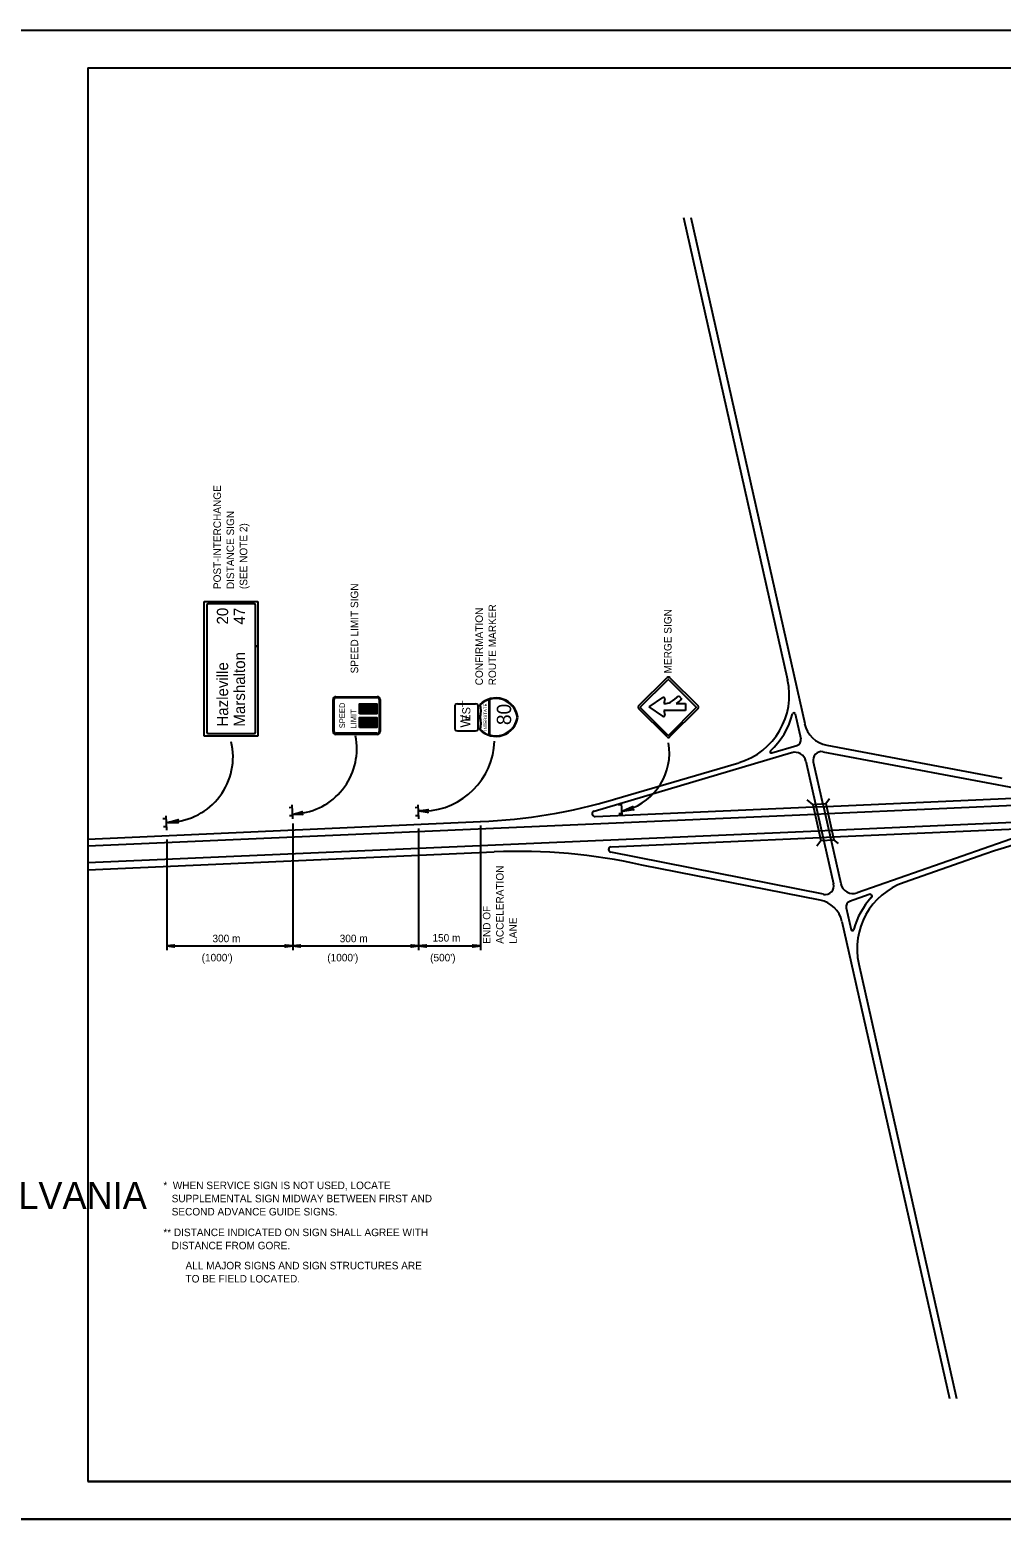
# Model space of a CAD drawing. Extents: x 640994 to 644422, y 298458 to 299646.
# Drawn here: x 641852 to 642240, y 299044 to 299646 of the extents above; entities that cross this region are included whole.
import ezdxf

# ---------------------------------------------------------------- set-up
doc = ezdxf.new("R2010")
doc.units = 0
for name, color, linetype in [('1', 7, 'Continuous'), ('2', 7, 'Continuous'), ('3', 7, 'Continuous'), ('XCS-GRID-MIN', 7, 'Continuous')]:
    doc.layers.add(name, color=color, linetype=linetype)

# ---------------------------------------------------------------- blocks, each defined once
blk = doc.blocks.new('RARROW')
at = {"layer": '3'}
blk.add_lwpolyline([(-2.2695, 0.285), (-2.184875, 0.12075), (0, 0), (-2.2695, 0.285), (-2.38575, 0.384625), (0, 0), (-2.183125, -0.108), (-2.262875, -0.2705), (0, 0), (-2.38575, -0.379125), (-2.262875, -0.2705)], dxfattribs=at)

msp = doc.modelspace()

# ---------------------------------------------------------------- linework, layer by layer
at = {"layer": '1'}
for p, q in [((641875.31, 299630.63), (642661.31, 299630.63)), ((641875.31, 299630.63), (641875.31, 299066.63)), ((642661.31, 299066.63), (641875.31, 299066.63)), ((641875.31, 299066.63), (642461.31, 299066.63))]:
    msp.add_line(p, q, dxfattribs=at)
at = {"layer": '2'}
for p, q in [((642112.94, 299570.88), (642154.44, 299386.5)), ((642115.94, 299570.88), (642161.31, 299369)), ((641921.81, 299364), (641921.81, 299417.75)), ((641921.81, 299417.75), (641943.19, 299417.75)), ((641922.81, 299416.25), (641922.81, 299365.5)), ((641941.69, 299416.75), (641923.31, 299416.75)), ((641942.19, 299399.88), (641942.19, 299416.25)), ((641943.19, 299417.75), (641943.19, 299399.88)), ((641942.19, 299399.88), (641943.19, 299399.88)), ((641943.19, 299399.88), (641942.19, 299399.88)), ((641942.19, 299365.5), (641942.19, 299399.88)), ((641943.19, 299399.88), (641943.19, 299364)), ((641932.44, 299390.88), (641932.44, 299390.88)), ((642095.06, 299376), (642106.44, 299387.38)), ((642095.81, 299375.63), (642106.69, 299386.5)), ((642107.06, 299386.5), (642117.94, 299375.63)), ((642107.44, 299387.38), (642118.81, 299376)), ((641973.19, 299365.88), (641973.19, 299378.63)), ((641973.56, 299365.88), (641973.56, 299378.63)), ((641974.31, 299379.63), (641990.81, 299379.63)), ((641974.31, 299379.38), (641990.81, 299379.38)), ((641991.56, 299378.63), (641991.56, 299365.88)), ((641991.94, 299378.63), (641991.94, 299365.88)), ((642035.44, 299364.5), (642035.44, 299378.63)), ((642035.69, 299364.5), (642035.69, 299378.63)), ((642099.31, 299375.63), (642104.69, 299379.38)), ((642105.56, 299378.63), (642105.06, 299377)), ((642111.06, 299380), (642112.31, 299378.75)), ((641987.69, 299372.88), (641983.69, 299376.88)), ((641986.94, 299372.88), (641983.69, 299376.25)), ((641986.19, 299372.88), (641983.69, 299375.5)), ((641985.56, 299372.88), (641983.69, 299374.88)), ((641984.94, 299372.88), (641983.69, 299374.13)), ((641984.19, 299372.88), (641983.69, 299373.38)), ((641988.44, 299372.88), (641984.44, 299376.88)), ((641989.06, 299372.88), (641985.06, 299376.88)), ((641989.81, 299372.88), (641985.81, 299376.88)), ((641990.44, 299372.88), (641986.44, 299376.88)), ((641990.69, 299373.38), (641987.19, 299376.88)), ((641990.69, 299374.13), (641987.94, 299376.88)), ((641990.69, 299374.75), (641988.69, 299376.88)), ((641990.69, 299375.38), (641989.31, 299376.88)), ((641990.69, 299376.13), (641990.06, 299376.88)), ((642021.94, 299366.63), (642021.94, 299376.38)), ((642022.81, 299376.88), (642029.94, 299376.88)), ((642030.94, 299376.38), (642030.94, 299366.63)), ((642031.94, 299376.5), (642031.94, 299376.5)), ((642106.44, 299363.63), (642095.06, 299375)), ((642106.69, 299364.38), (642095.81, 299375.25)), ((642104.69, 299371.88), (642099.31, 299375.63)), ((642105.06, 299377), (642105.44, 299377)), ((642113.81, 299374.25), (642105.06, 299374.25)), ((642105.06, 299374.25), (642105.56, 299372.63)), ((642117.94, 299375.25), (642107.06, 299364.38)), ((642117.94, 299375.25), (642107.06, 299364.38)), ((642118.81, 299375), (642107.44, 299363.63)), ((642110.06, 299377), (642113.81, 299377)), ((642113.81, 299377), (642113.81, 299374.25)), ((642157.56, 299372.88), (642159.81, 299362.88)), ((641982.56, 299372.13), (641982.56, 299372.13)), ((641987.69, 299367.38), (641983.69, 299371.38)), ((641986.94, 299367.38), (641983.69, 299370.75)), ((641986.19, 299367.38), (641983.69, 299370)), ((641985.56, 299367.38), (641983.69, 299369.38)), ((641984.94, 299367.38), (641983.69, 299368.63)), ((641984.19, 299367.38), (641983.69, 299367.88)), ((641988.44, 299367.38), (641984.44, 299371.38)), ((641989.06, 299367.38), (641985.06, 299371.38)), ((641989.81, 299367.38), (641985.81, 299371.38)), ((641990.44, 299367.38), (641986.44, 299371.38)), ((641990.69, 299367.88), (641987.19, 299371.38)), ((641990.69, 299368.63), (641987.94, 299371.38)), ((641990.69, 299369.25), (641988.69, 299371.38)), ((641990.69, 299369.88), (641989.31, 299371.38)), ((641990.69, 299370.63), (641990.06, 299371.38)), ((642026.44, 299371.5), (642026.44, 299371.5)), ((642031.94, 299371.5), (642031.94, 299371.5)), ((642039.31, 299371.5), (642039.31, 299371.5)), ((641943.19, 299364), (641921.81, 299364)), ((641923.31, 299365), (641941.69, 299365)), ((641990.81, 299365.13), (641974.31, 299365.13)), ((641990.81, 299364.63), (641974.31, 299364.63)), ((642029.94, 299366), (642022.81, 299366)), ((642031.94, 299366.5), (642031.94, 299366.5)), ((642077.31, 299334), (642156.06, 299357.38)), ((642148.19, 299357.25), (642158.19, 299360.25)), ((642168.56, 299357.75), (642253.56, 299341.75)), ((642170.19, 299360.38), (642239.94, 299347.25)), ((642170.44, 299333.13), (642661.31, 299354.84)), ((642085.44, 299338.88), (642135.06, 299353.38)), ((642161.78, 299354.04), (642165.56, 299336.88)), ((642164.72, 299353.7), (642168.56, 299336.75)), ((642171.94, 299326.5), (642661.31, 299347.96)), ((641956.69, 299336.5), (641956.94, 299331)), ((642006.94, 299336.5), (642007.19, 299331)), ((642088.06, 299336.5), (642087.06, 299336.38)), ((642088.06, 299337.5), (642088.31, 299332)), ((642164.56, 299336.75), (642162.31, 299338.5)), ((642164.56, 299336.75), (642169.69, 299337.13)), ((642164.56, 299336.75), (642167.81, 299322.38)), ((642165.56, 299336.88), (642172.81, 299305)), ((642168.56, 299337), (642175.69, 299305.13)), ((642169.69, 299337.13), (642171.19, 299339.13)), ((642169.69, 299337.13), (642172.94, 299322.63)), ((642169.81, 299335.88), (642253.44, 299339.63)), ((641875.31, 299320.21), (642165.44, 299332.88)), ((641906.44, 299331), (641905.31, 299331)), ((641906.44, 299332.13), (641906.69, 299326.5)), ((641956.69, 299335.5), (641955.69, 299335.38)), ((641956.94, 299332.13), (641955.81, 299332.13)), ((642006.94, 299335.5), (642005.94, 299335.38)), ((642007.19, 299332.13), (642006.06, 299332.13)), ((642077.69, 299331.88), (642164.81, 299335.75)), ((642088.31, 299333), (642087.19, 299333)), ((642164.81, 299335.75), (642169.81, 299335.88)), ((642165.44, 299332.88), (642170.44, 299333.13)), ((641875.31, 299322.84), (642031.94, 299329.88)), ((641875.31, 299313.59), (642166.81, 299326.25)), ((641906.56, 299327.75), (641905.56, 299327.75)), ((641957.06, 299329.13), (641957.06, 299278.63)), ((642007.31, 299328.75), (642007.31, 299328.75)), ((642007.31, 299327.13), (642007.31, 299278.63)), ((642031.94, 299328.38), (642031.94, 299278.63)), ((642166.81, 299326.25), (642171.94, 299326.5)), ((642172.56, 299323.75), (642248.94, 299327.13)), ((642249.31, 299324.88), (642182.23, 299301.42)), ((641906.81, 299324.38), (641906.81, 299324.38)), ((641906.81, 299322.75), (641906.81, 299278.63)), ((642084.19, 299319.75), (642167.44, 299323.5)), ((642166.19, 299320.25), (642167.81, 299322.38)), ((642167.44, 299323.5), (642172.56, 299323.75)), ((642167.81, 299322.38), (642172.94, 299322.63)), ((642174.81, 299321.13), (642172.94, 299322.63)), ((641875.31, 299310.59), (642037.44, 299317.75)), ((642168.81, 299300.88), (642083.94, 299317.63)), ((642167.44, 299298.5), (642096.31, 299312.5)), ((642233.19, 299316.88), (642200.94, 299305.63)), ((642186.98, 299300.74), (642179.19, 299298)), ((642177.83, 299295.44), (642179.81, 299286.75)), ((642176.19, 299290), (642219.06, 299099.75)), ((641906.81, 299280.25), (641957.06, 299280.25)), ((641957.06, 299280.25), (642007.31, 299280.25)), ((642007.31, 299280.25), (642031.94, 299280.25)), ((642182.94, 299273), (642221.81, 299099.75))]:
    msp.add_line(p, q, dxfattribs=at)
for points in [[(641983.69, 299372.88), (641983.69, 299376.88), (641990.69, 299376.88), (641990.69, 299372.88)], [(641983.69, 299367.38), (641983.69, 299371.38), (641990.69, 299371.38), (641990.69, 299367.38)]]:
    msp.add_lwpolyline(points, close=True, dxfattribs=at)
for points in [[(641911.32, 299329.58), (641911.07, 299329.71), (641907.19, 299329.58), (641911.32, 299329.58), (641911.44, 299329.33), (641907.19, 299329.58), (641911.07, 299330.21), (641911.19, 299330.46), (641907.19, 299329.58), (641911.32, 299330.71), (641911.19, 299330.46)], [(641960.83, 299332.82), (641960.66, 299333.04), (641957.29, 299332.7), (641960.83, 299332.82), (641961.1, 299332.74), (641957.29, 299332.7), (641960.6, 299333.41), (641960.68, 299333.68), (641957.29, 299332.7), (641960.88, 299333.97), (641960.68, 299333.68)], [(642010.81, 299333.63), (642010.69, 299333.88), (642007.31, 299334.13), (642010.81, 299333.63), (642011.06, 299333.5), (642007.31, 299334.13), (642010.69, 299334.25), (642010.81, 299334.5), (642007.31, 299334.13), (642011.06, 299334.75), (642010.81, 299334.5)], [(642092.94, 299334.75), (642092.56, 299335), (642088.81, 299334), (642092.94, 299334.75), (642093.19, 299334.63), (642088.81, 299334), (642092.56, 299335.38), (642092.56, 299335.75), (642088.81, 299334), (642092.69, 299335.88), (642092.56, 299335.75)], [(641909.67, 299279.89), (641909.56, 299280.1), (641906.81, 299280.25), (641909.67, 299279.89), (641909.81, 299279.77), (641906.81, 299280.25), (641909.56, 299280.39), (641909.66, 299280.59), (641906.81, 299280.25), (641909.81, 299280.73), (641909.66, 299280.59)], [(641954.21, 299280.61), (641954.31, 299280.4), (641957.06, 299280.25), (641954.21, 299280.61), (641954.06, 299280.74), (641957.06, 299280.25), (641954.32, 299280.12), (641954.22, 299279.91), (641957.06, 299280.25), (641954.06, 299279.77), (641954.22, 299279.91)], [(641959.92, 299279.89), (641959.81, 299280.1), (641957.06, 299280.25), (641959.92, 299279.89), (641960.06, 299279.77), (641957.06, 299280.25), (641959.81, 299280.39), (641959.91, 299280.59), (641957.06, 299280.25), (641960.06, 299280.73), (641959.91, 299280.59)], [(642004.46, 299280.61), (642004.56, 299280.4), (642007.31, 299280.25), (642004.46, 299280.61), (642004.31, 299280.74), (642007.31, 299280.25), (642004.57, 299280.12), (642004.47, 299279.91), (642007.31, 299280.25), (642004.31, 299279.77), (642004.47, 299279.91)], [(642010.17, 299279.89), (642010.06, 299280.1), (642007.31, 299280.25), (642010.17, 299279.89), (642010.31, 299279.77), (642007.31, 299280.25), (642010.06, 299280.39), (642010.16, 299280.59), (642007.31, 299280.25), (642010.31, 299280.73), (642010.16, 299280.59)], [(642029.08, 299280.61), (642029.19, 299280.4), (642031.94, 299280.25), (642029.08, 299280.61), (642028.94, 299280.74), (642031.94, 299280.25), (642029.19, 299280.12), (642029.09, 299279.91), (642031.94, 299280.25), (642028.94, 299279.77), (642029.09, 299279.91)]]:
    msp.add_lwpolyline(points, dxfattribs=at)
for centre, radius, start, end in [((641923.31, 299416.25), 0.5, 90, 180), ((641941.69, 299416.25), 0.5, 0, 90), ((642106.95, 299386.86), 0.699, 45, 135), ((642106.95, 299386.86), 0.699, 45, 135), ((642106.87, 299386.34), 0.25, 45, 135), ((642127.17, 299380.32), 27.99, 286.46389, 12.68034), ((641974.31, 299378.56), 1.13, 90, 180), ((641974.31, 299378.56), 0.75, 90, 180), ((641990.81, 299378.56), 1.13, 0, 90), ((641990.81, 299378.56), 0.75, 0, 90), ((642038.08, 299370.27), 8.94, 8.1301, 135), ((642038.08, 299370.27), 8.75, 107.54623, 134.30764), ((642038.08, 299370.27), 8.69, 8.1301, 105.95434), ((642105, 299378.83), 0.582, 343.79783, 121.66937), ((642099.68, 299391.84), 16.39, 299.43702, 313.88494), ((642099.37, 299392.22), 18.68, 305.14146, 313.88923), ((642021.79, 299374.07), 10.28, 345.74997, 14.25003), ((642021.79, 299374.07), 10.46, 346.01104, 13.6595), ((642095.58, 299375.5), 0.699, 135, 225), ((642095.58, 299375.5), 0.699, 135, 225), ((642095.98, 299375.44), 0.25, 135, 225), ((642105, 299372.42), 0.582, 238.443, 16.08981), ((642105.38, 299381.67), 4.73, 269.77573, 299.88968), ((642117.75, 299375.46), 0.25, 309.28941, 45), ((642118.31, 299375.5), 0.699, 315, 45), ((642118.31, 299375.5), 0.699, 315, 45), ((642127.17, 299380.32), 30.23, 312.60339, 345.66334), ((642157.01, 299372.68), 0.566, 20.17087, 164.59507), ((642021.79, 299369.01), 10.28, 345.74997, 14.25003), ((642038.08, 299372.8), 8.94, 225, 351.8699), ((642021.79, 299369.01), 10.46, 346.3405, 13.98896), ((642038.08, 299372.8), 8.69, 254.04566, 351.8699), ((642172.22, 299371.38), 11.2, 192.68035, 259.39124), ((641907.32, 299355.63), 25.94, 272.1007, 13.60606), ((641923.31, 299365.5), 0.5, 180, 270), ((641941.69, 299365.5), 0.5, 270, 0), ((641956.7, 299358.88), 25.94, 277.01253, 11.46002), ((641974.31, 299365.81), 1.13, 180, 270), ((641974.31, 299365.81), 0.75, 180, 270), ((641990.81, 299365.81), 1.13, 270, 0), ((641990.81, 299365.81), 0.75, 270, 0), ((642008.57, 299363.1), 29.05, 272.21751, 357.78249), ((642038.08, 299372.8), 8.75, 225.69236, 252.45377), ((642083.58, 299357.28), 23.75, 286.93284, 9.61942), ((642106.95, 299364.13), 0.699, 225, 315), ((642106.95, 299364.13), 0.699, 225, 315), ((642106.87, 299364.54), 0.25, 225, 315), ((642106.87, 299364.54), 0.25, 225, 315), ((642157.59, 299362.45), 2.24, 286.46377, 12.68123), ((642147.93, 299357.72), 0.455, 130.53264, 302.14851), ((642157.41, 299353.06), 4.48, 12.68, 106.46376), ((642168, 299354.44), 3.36, 79.39121, 192.6799), ((642022.07, 299553.59), 223.94, 272.5187, 286.46393), ((642077.65, 299332.99), 1.12, 106.46381, 272.51876), ((642307.05, 299105.48), 223.94, 92.51875, 109.26329), ((642084.22, 299318.71), 1.12, 92.51875, 257.34197), ((642047.27, 299094.05), 223.94, 77.3419, 92.51875), ((642169.44, 299304.27), 3.5, 259.33581, 12.57469), ((642180.6, 299306.15), 5, 192.27026, 289.0723), ((642210.18, 299279.19), 27.99, 109.26337, 192.68034), ((642187.43, 299300.15), 0.739, 298.83597, 127.17309), ((642165.26, 299287.54), 11.2, 12.68046, 78.84184), ((642180.02, 299295.93), 2.24, 109.26352, 192.68012), ((642210.18, 299279.19), 30.23, 137.59817, 165.05653), ((642180.35, 299287.03), 0.623, 204.68777, 356.14813)]:
    msp.add_arc(centre, radius, start, end, dxfattribs=at)
for centre, major_axis, start_param, end_param in [((642022.83, 299376.3), (-0.896, 0), 4.712389, 6.283185), ((642030, 299376.3), (-0.896, 0), 3.141593, 4.712389), ((642022.83, 299366.63), (0.896, 0), 3.141593, 4.712389), ((642030, 299366.63), (0.896, 0), 4.712389, 6.283185)]:
    msp.add_ellipse(centre, major_axis=major_axis, ratio=0.6, start_param=start_param, end_param=end_param, dxfattribs=at)
at = {"layer": 'XCS-GRID-MIN'}
for points in [[(641835.31, 299645.63), (642676.31, 299645.63), (642676.31, 299051.63), (641835.31, 299051.63)], [(641835.31, 299051.63), (642676.31, 299051.63), (642676.31, 298457.63), (641835.31, 298457.63)]]:
    msp.add_lwpolyline(points, close=True, dxfattribs=at)

# ---------------------------------------------------------------- block references
at = {"layer": '2', "xscale": 1.2574347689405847, "yscale": 1.3092961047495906}
msp.add_blockref('RARROW', (641957.06, 299280.25), dxfattribs=at)

# ---------------------------------------------------------------- texts
at = {"layer": '1'}
msp.add_text('COMMONWEALTH OF PENNSYLVANIA', height=10.7828, dxfattribs=at).set_placement((641632.9, 299175.36))
at = {"layer": '2'}
for s, height, p in [('POST-INTERCHANGE', 3, (641928.44, 299422.63)), ('DISTANCE SIGN', 3, (641933.69, 299422.63)), ('(SEE NOTE 2)', 3, (641938.94, 299422.63)), ('SPEED LIMIT SIGN', 3, (641983.19, 299389)), ('20', 4.5, (641931.31, 299408.5)), ('47', 4.5, (641938.06, 299408.5)), ('CONFIRMATION', 3, (642032.94, 299384.25)), ('ROUTE MARKER', 3, (642038.19, 299384.25)), ('MERGE SIGN', 3, (642108.19, 299389)), ('Marshalton     ', 4.5, (641938.06, 299367.75)), ('Hazleville     ', 4.5, (641931.31, 299367.75)), ('SPEED', 2.249, (641977.94, 299367.13)), ('LIMIT', 2.249, (641982.44, 299367)), ('EST', 3.25, (642027.94, 299369.75)), ('INTERSTATE', 1.264, (642034.56, 299366.13)), ('80', 5.69, (642044.19, 299368.38)), ('W', 4, (642027.94, 299367.38)), ('ACCELERATION', 3, (642041.19, 299281.13)), ('END OF', 3, (642035.94, 299281.13)), ('LANE', 3, (642046.44, 299281.13))]:
    msp.add_text(s, height=height, rotation=90, dxfattribs=at).set_placement(p)
for s, p in [('300 m', (641925.06, 299281.75)), ('300 m', (641975.81, 299281.75)), ('150 m', (642012.81, 299282)), ("(1000')", (641920.74, 299274.12)), ("(1000')", (641970.86, 299274.12)), ("(500')", (642011.89, 299274.12)), ('*  WHEN SERVICE SIGN IS NOT USED, LOCATE', (641905.44, 299183.25)), ('   SUPPLEMENTAL SIGN MIDWAY BETWEEN FIRST AND', (641905.44, 299178)), ('   SECOND ADVANCE GUIDE SIGNS.', (641905.44, 299172.75)), ('** DISTANCE INDICATED ON SIGN SHALL AGREE WITH', (641905.44, 299164.5)), ('   DISTANCE FROM GORE.', (641905.44, 299159.25)), ('ALL MAJOR SIGNS AND SIGN STRUCTURES ARE', (641914.31, 299151.25)), ('TO BE FIELD LOCATED.', (641914.31, 299146))]:
    msp.add_text(s, height=3, dxfattribs=at).set_placement(p)

doc.saveas('drawing.dxf')
